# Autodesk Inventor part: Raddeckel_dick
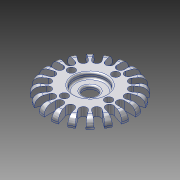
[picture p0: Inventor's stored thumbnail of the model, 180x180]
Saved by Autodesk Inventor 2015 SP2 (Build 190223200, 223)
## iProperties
Created: 2012-07
Part Number: Raddeckel_dick
Material: Aluminium 6061
Document SubType Name: Modeling
Designer: rYan
Mass: 5.08801 g
Surface Area: 32.6854 cm^2
Volume: 1.8775 cm^3
Density: 2.71 g/cm^3
Appearance: Aluminium - flach
Author: rYan
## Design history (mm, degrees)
sketch "Skizze1"
  geometry: C1 r 24.5 at (0, 0); A1 r 22.5 centre (0, 0) between (2, 22.411) and (-2, 22.411) reference; 1 further point
  constraints: 2 centre point, 2 point on circle, 1 coincident, 4 other
  dimensions: "d28" = 49 diameter of C1
extrude "Extrusion1" new body sketch "Skizze1" distance "d0" = 5; taper "d1" = 0 deg
fillet "Rundung1" dims "d31" = 4
sketch "Skizze2"
  geometry: L1 (-2.2, 24.5)-(2.2, 24.5); L2 (2.2, 24.5)-(2.2, 17.7); L3 (-2.2, 24.5)-(-2.2, 17.7); L4 (0, 31.333)-(0, -31.333); L5 (0, 43.866)-(0, -43.866) reference; C1 r 15.5 at (0, 0); C2 r 24.5 at (0, 0) reference; A1 r 2.2 centre (0, 17.7) between (-2.2, 17.7) and (2.2, 17.7); 2 further points
  constraints: 8 end point, 4 tangent, 2 centre point, 2 coincident, 2 point on circle, 1 collinear, 1 midpoint, 1 parallel, 1 perpendicular, 1 other
  dimensions: "d2" = 31 diameter of C1; "d3" = 4.4 distance between parallel lines of L2 L3
extrude "Extrusion2" cut sketch "Skizze2" stored distance "d4" = 2; taper "d5" = 0 deg
sketch "Skizze3"
  geometry: 1 further point
hole "Bohrung1" sketch "Skizze3" at (0, 0) diameter "d9" = 8; stored, may be unused: countersink angle "d13" = 90 deg, drill point angle "d15" = 118 deg; dims "d10" = 6, "d11" = 18, "d12" = 3, "d14" = 8
sketch "Skizze5" dims "d29" = 26
  geometry: L1 (0, 34.3)-(0, -34.3) reference; L2 (-34.3, 0)-(34.3, 0) reference; L3 (0, 0)-(-2.034, -12.84); 1 further point
  constraints: 2 end point, 1 coincident, 3 other
  dimensions: "d30" = 9 deg angle of L1 L3
hole "Bohrung2" sketch "Skizze5" at (-2.034, -12.84) diameter "d18" = 2.1; stored, may be unused: countersink angle "d22" = 90 deg, drill point angle "d24" = 118 deg; dims "d19" = 6, "d20" = 4.4, "d21" = 3, "d23" = 8
pattern_circular "Runde Anordnung2" dims angle "d26" = 360 deg
fillet "Rundung2" dims "d32" = 1
node "Volumenkörper1"
pattern_circular "Runde Anordnung1" dims angle "d7" = 360 deg
